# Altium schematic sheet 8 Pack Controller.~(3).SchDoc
size B
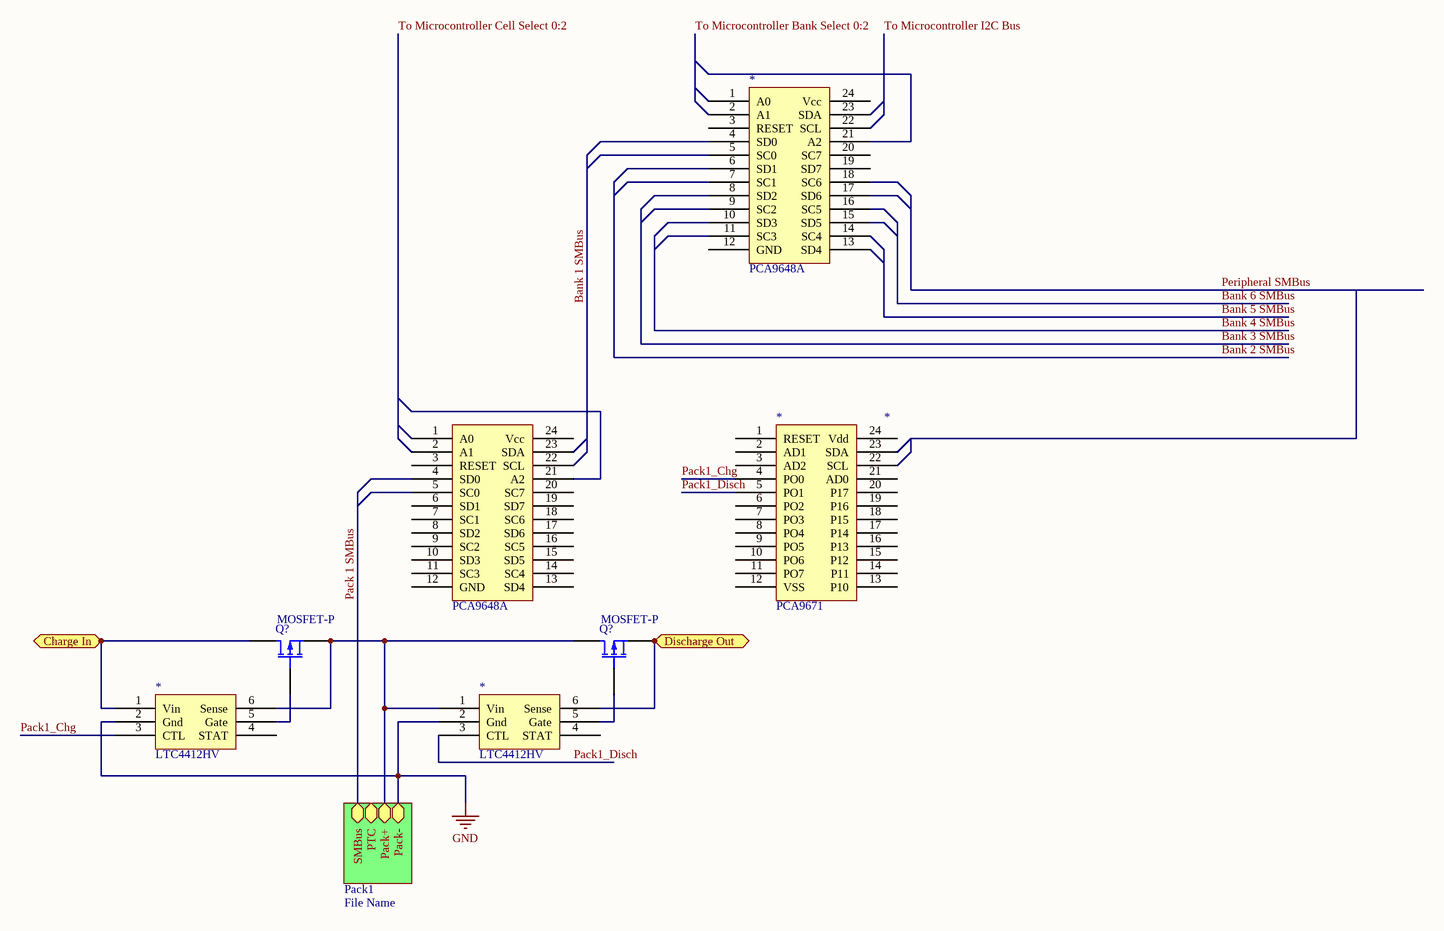
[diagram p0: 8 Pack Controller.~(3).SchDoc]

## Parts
(Parts that share a designator on the sheet are numbered #1, #2 ... from top to bottom, then left to right.)
*#1  PCA9648A
*#2  PCA9648A
*#3  PCA9671
*#4  LTC4412HV
*#5  LTC4412HV
Q?#1  MOSFET-P  [BCY-W3/B.8]
Q?#2  MOSFET-P  [BCY-W3/B.8]

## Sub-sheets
Pack1 = File Name: SMBus, PTC, Pack+, Pack-

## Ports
Charge In, Discharge Out

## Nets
GND: *#4.2(Gnd) *#5.2(Gnd) ; sheet Pack1/Pack-
Charge In: *#4.1(Vin) Q?#1.1(D) ; port Charge In
Discharge Out: *#5.6(Sense) Q?#2.3(S) ; port Discharge Out
Pack1_Chg: *#3.4(PO0) *#4.3(CTL)
Pack1_Disch: *#3.5(PO1) *#5.3(CTL)
Net*#4_5: *#4.5(Gate) Q?#1.2(G)
Net*#4_6: *#4.6(Sense) *#5.1(Vin) Q?#1.3(S) Q?#2.1(D) ; sheet Pack1/Pack+
Net*#5_5: *#5.5(Gate) Q?#2.2(G)

Not connected (* = marked no-connect by the designer): *#1 1(A0) 2(A1) 3(RESET) 4(SD0) 5(SC0) 6(SD1) 7(SC1) 8(SD2) 9(SC2) 10(SD3) 11(SC3) 12(GND) 13(SD4) 14(SC4) 15(SD5) 16(SC5) 17(SD6) 18(SC6) 19(SD7) 20(SC7) 21(A2) 22(SCL) 23(SDA) 24(Vcc); *#2 1(A0) 2(A1) 3(RESET) 4(SD0) 5(SC0) 6(SD1) 7(SC1) 8(SD2) 9(SC2) 10(SD3) 11(SC3) 12(GND) 13(SD4) 14(SC4) 15(SD5) 16(SC5) 17(SD6) 18(SC6) 19(SD7) 20(SC7) 21(A2) 22(SCL) 23(SDA) 24(Vcc); *#3 1(RESET) 2(AD1) 3(AD2) 6(PO2) 7(PO3) 8(PO4) 9(PO5) 10(PO6) 11(PO7) 12(VSS) 13(P10) 14(P11) 15(P12) 16(P13) 17(P14) 18(P15) 19(P16) 20(P17) 21(AD0) 22(SCL) 23(SDA) 24(Vdd); *#4 4(STAT); *#5 4(STAT)

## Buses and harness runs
bus Bank 1 SMBus
bus Bank 2 SMBus
bus Bank 3 SMBus
bus Bank 4 SMBus
bus Bank 5 SMBus
bus Bank 6 SMBus
bus Pack 1 SMBus = sheet Pack1/SMBus
bus Peripheral SMBus
bus To Microcontroller Bank Select 0:2
bus To Microcontroller Cell Select 0:2
bus To Microcontroller I2C Bus

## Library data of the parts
Q?#1 Q?#2 = MOSFET-P: P-Channel MOSFET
